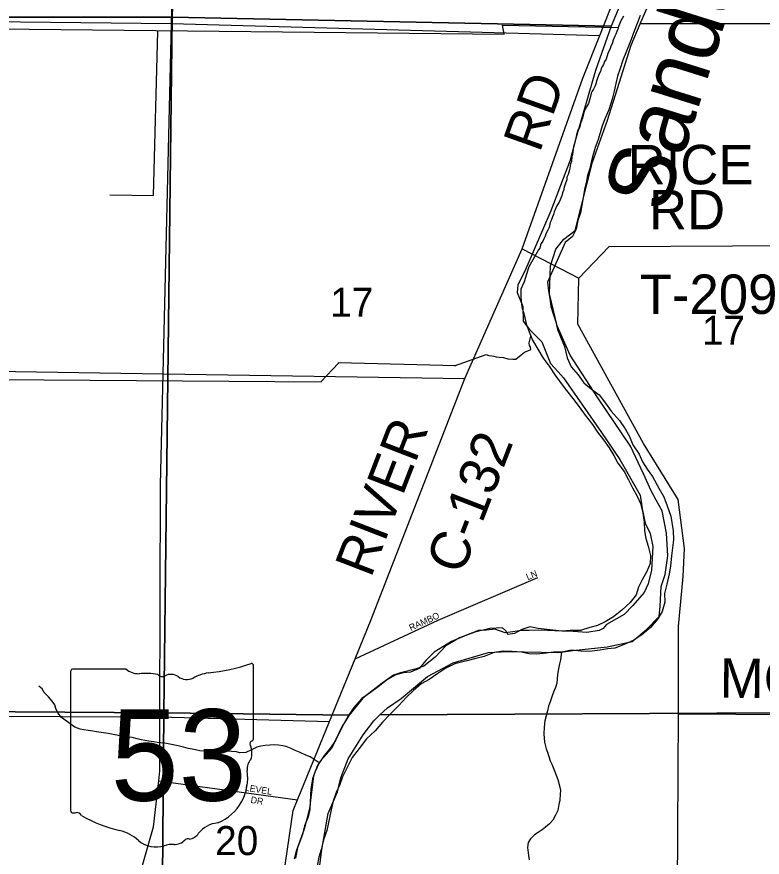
# Model space of a CAD drawing. Extents: x 1588073 to 2013523, y 1090242 to 1357120.
# Drawn here: x 1783629 to 1789302, y 1201342 to 1207738 of the extents above; entities that cross this region are included whole.
import ezdxf

# ---------------------------------------------------------------- set-up
doc = ezdxf.new("R2010")
doc.units = 0
for name, color, linetype in [('GM_X_County_Road', 7, 'Continuous'), ('GM_X_County_Road_Text', 7, 'Continuous'), ('GM_X_Major_River', 7, 'Continuous'), ('GM_X_Major_River_Text', 7, 'Continuous'), ('GM_X_Minor_River', 7, 'Continuous'), ('GM_X_Section', 7, 'Continuous'), ('GM_X_Section_Text', 7, 'Continuous'), ('GM_X_State_Location', 7, 'Continuous'), ('GM_X_State_Route', 7, 'Continuous'), ('GM_X_State_Shield', 7, 'Continuous'), ('GM_X_Township_Road', 7, 'Continuous'), ('GM_X_Township_Road_Text', 7, 'Continuous'), ('GM_X_Township_Subdivision', 7, 'Continuous'), ('GM_X_Township_Subdivision_Text', 7, 'Continuous')]:
    doc.layers.add(name, color=color, linetype=linetype)

msp = doc.modelspace()

# ---------------------------------------------------------------- linework, layer by layer
at = {"layer": 'GM_X_County_Road'}
for points in [[(1787474.9, 1205971.8), (1787936, 1207270.8), (1788064.7, 1207596.9), (1788700.1, 1209207.2), (1788763.4, 1211956.2), (1788825.7, 1212115.9), (1789120.8, 1212441.4), (1789759.7, 1212989.5)], [(1787038, 1204985.7), (1787474.9, 1205971.8)], [(1779562.1, 1205007.3), (1780843.4, 1205083.3), (1782009.9, 1205064.2), (1784742.1, 1205019.5)], [(1784742.1, 1205019.5), (1787038, 1204985.7)], [(1785390.7, 1200052.5), (1785574.5, 1200475), (1785618.1, 1200578.8), (1785660.7, 1201214.2), (1785731.4, 1201696.7), (1785765.2, 1201779.3), (1786008.7, 1202375), (1786203.9, 1202852.3), (1786326.5, 1203152), (1787038, 1204985.7)]]:
    msp.add_lwpolyline(points, dxfattribs=at)
at = {"layer": 'GM_X_Major_River'}
for points in [[(1788245.2, 1207742.7), (1788226.8, 1207706.8), (1788216.5, 1207682.8), (1788208.3, 1207664.9), (1788204.1, 1207642.9), (1788195.9, 1207626.9), (1788187.7, 1207604.9), (1788179.5, 1207591), (1788167.2, 1207561.1), (1788158.9, 1207533.1), (1788148.7, 1207515.1), (1788144.5, 1207497.1), (1788126.1, 1207459.2), (1788113.6, 1207415.3), (1788101.4, 1207397.3), (1788093.1, 1207375.4), (1788085, 1207361.4), (1788076.8, 1207345.5), (1788070.6, 1207321.5), (1788058.3, 1207297.6), (1788043.8, 1207255.6), (1788035.5, 1207227.6), (1788029.4, 1207211.7), (1788017.1, 1207187.7), (1788006.9, 1207171.8), (1788000.7, 1207155.8), (1787994.5, 1207131.8), (1787979.9, 1207077.9), (1787965.6, 1207051.9), (1787947.2, 1207016.1), (1787934.7, 1206966.1), (1787922.4, 1206934.1), (1787912, 1206896.2), (1787899.7, 1206876.2), (1787889.3, 1206840.3), (1787878.8, 1206792.3), (1787870.6, 1206766.3), (1787866.4, 1206748.3), (1787864.2, 1206730.3), (1787857.8, 1206690.2), (1787853.6, 1206674.3), (1787849.2, 1206636.2), (1787843, 1206620.2), (1787834.6, 1206574.2), (1787830.4, 1206556.2), (1787824.2, 1206538.3), (1787815.9, 1206516.3), (1787813.7, 1206496.3), (1787803.5, 1206472.3), (1787795.2, 1206442.3), (1787788.9, 1206416.3), (1787782.7, 1206398.4), (1787776.5, 1206376.4), (1787768.3, 1206358.4), (1787764.1, 1206344.4), (1787755.9, 1206326.5), (1787739.6, 1206298.6), (1787727.3, 1206276.7), (1787719.1, 1206254.7), (1787712.9, 1206232.7), (1787704.7, 1206214.8), (1787694.4, 1206186.8), (1787688.2, 1206172.8), (1787679.8, 1206134.8), (1787669.6, 1206112.9), (1787655.3, 1206087), (1787649.1, 1206069), (1787638.9, 1206047), (1787632.7, 1206031.1), (1787620.5, 1206013.1), (1787614.3, 1205999.2), (1787608.1, 1205977.2), (1787597.9, 1205963.3)], [(1788373.5, 1207747.4), (1788348.9, 1207687.5), (1788326.2, 1207629.6), (1788303.5, 1207565.7), (1788268.6, 1207475.9), (1788239.8, 1207408), (1788217.1, 1207338.1), (1788200.5, 1207286.1), (1788187.9, 1207230.1), (1788175.3, 1207172.1), (1788158.7, 1207110.2), (1788133.8, 1207030.3), (1788107.1, 1206966.4), (1788084.5, 1206908.5), (1788067.9, 1206854.5), (1788051.3, 1206796.6), (1788030.7, 1206742.7), (1788016.2, 1206690.7), (1787999.5, 1206632.7), (1787989, 1206582.7), (1787972.5, 1206530.8), (1787961.9, 1206472.8), (1787949.3, 1206422.8), (1787938.7, 1206362.8), (1787930.1, 1206304.7), (1787919.5, 1206246.7), (1787898.9, 1206188.8), (1787886.2, 1206120.8), (1787857.5, 1206064.9), (1787801, 1206021.4), (1787666.8, 1205717.8)], [(1787597.9, 1205963.3), (1787526.5, 1205835.7), (1787507.9, 1205779.8), (1787489.3, 1205721.8), (1787464.6, 1205663.9), (1787464, 1205601.8), (1787473.3, 1205531.6), (1787488.8, 1205469.3), (1787506.1, 1205401), (1787527.6, 1205340.6), (1787553, 1205278.2), (1787594.4, 1205207.7), (1787633.8, 1205141.1), (1787679.3, 1205078.6), (1787722.8, 1205014), (1787764.3, 1204957.5), (1787811.8, 1204894.9), (1787859.3, 1204834.3), (1787908.8, 1204769.6), (1787954.3, 1204707.1), (1788009.7, 1204634.4), (1788049.2, 1204577.9), (1788094.7, 1204519.3), (1788136.2, 1204456.8), (1788173.7, 1204398.2), (1788203.2, 1204339.8), (1788250.7, 1204277.2), (1788284.1, 1204212.8), (1788315.6, 1204154.3), (1788349.1, 1204089.9), (1788376.6, 1204033.5), (1788393.9, 1203963.1), (1788403.2, 1203892.9), (1788406.6, 1203824.7), (1788416, 1203768.5), (1788433.5, 1203708.2), (1788452.8, 1203637.9), (1788448.2, 1203577.8), (1788423.5, 1203515.9), (1788388.8, 1203452.1), (1788360.2, 1203396.2), (1788341.6, 1203338.3), (1788296.9, 1203280.6), (1788234.2, 1203221.1), (1788169.5, 1203171.6), (1788107, 1203134.1), (1788048.6, 1203106.6), (1787990.3, 1203089.2), (1787919.9, 1203067.8), (1787839.7, 1203068.6), (1787779.5, 1203063.2), (1787667.3, 1203068.3), (1787597.2, 1203071), (1787527, 1203067.7), (1787466.8, 1203066.3), (1787402.6, 1203056.9), (1787346.4, 1203049.4), (1787266.5, 1203078.3), (1787204.3, 1203070.9), (1787142.1, 1203067.5), (1787063.6, 1203038.2), (1787003.2, 1203010.7), (1786936.8, 1202983.3), (1786870.2, 1202943.8), (1786805.7, 1202902.4), (1786740.9, 1202838.9), (1786690.2, 1202779.3), (1786625.7, 1202749.8), (1786569.6, 1202744.4), (1786513.3, 1202728.9), (1786450.8, 1202693.4), (1786378, 1202638), (1786319.5, 1202594.5), (1786254.9, 1202551), (1786194.1, 1202481.5), (1786153.4, 1202419.7), (1786116.6, 1202355.9), (1786083.9, 1202290.1), (1786053.2, 1202230.3), (1786016.6, 1202174.5), (1785969.9, 1202118.8), (1785929.3, 1202061.1), (1785898.6, 1201995.3), (1785877.9, 1201939.3), (1785867.2, 1201863.3), (1785862.2, 1201763.1), (1785857.6, 1201705), (1785845, 1201649), (1785818.3, 1201581.1), (1785803.6, 1201515.1), (1785780.9, 1201455.2), (1785756.3, 1201395.3), (1785739.6, 1201327.3)], [(1787666.8, 1205717.8), (1787675, 1205651.8), (1787684.5, 1205593.6), (1787693.9, 1205533.4), (1787711.4, 1205477.1), (1787730.8, 1205416.8), (1787744.3, 1205358.5), (1787767.8, 1205302.2), (1787797.1, 1205229.7), (1787818.3, 1205141.3), (1787847.7, 1205074.9), (1787901.2, 1205012.2), (1787944.7, 1204951.7), (1788000.4, 1204907.1), (1788062.1, 1204860.3), (1788109.5, 1204797.8), (1788153, 1204737.2), (1788214.5, 1204664.4), (1788260, 1204601.8), (1788291.4, 1204543.4), (1788316.9, 1204481), (1788364.3, 1204408.4), (1788391.8, 1204352), (1788427.3, 1204295.6), (1788466.8, 1204239), (1788514.1, 1204150.4), (1788553.5, 1204085.8), (1788578.9, 1204017.4), (1788606.2, 1203937), (1788625.1, 1203826.6), (1788626.4, 1203758.4), (1788619.8, 1203696.3), (1788611.2, 1203636.3), (1788604.4, 1203558.2), (1788593.8, 1203498.2), (1788577, 1203420.2), (1788558.2, 1203348.2), (1788559.5, 1203282), (1788540.8, 1203212.1), (1788506.2, 1203156.3), (1788451.4, 1203090.7), (1788386.7, 1203035.2), (1788324.1, 1202993.7), (1788251.6, 1202960.3), (1788181.2, 1202933), (1788125, 1202927.5), (1788068.8, 1202918), (1787988.5, 1202906.8), (1787922.4, 1202909.5), (1787850.3, 1202918.2), (1787776, 1202902.9), (1787713.8, 1202901.5), (1787657.6, 1202896), (1787587.3, 1202886.7), (1787525.2, 1202889.3), (1787469.2, 1202901.9), (1787399.1, 1202908.6), (1787331, 1202911.3), (1787262.7, 1202899.9), (1787186.2, 1202870.6), (1787121.9, 1202855.2), (1787053.6, 1202835.8), (1786963.2, 1202812.6), (1786892.7, 1202781.3), (1786832.1, 1202739.8), (1786767.5, 1202694.3), (1786707, 1202660.8), (1786648.4, 1202611.3), (1786591.8, 1202557.7), (1786535, 1202496.1), (1786468.2, 1202428.6), (1786411.5, 1202369.1), (1786356.7, 1202303.5), (1786289.9, 1202242), (1786233.1, 1202170.4), (1786180.3, 1202100.8), (1786141.4, 1202018.9), (1786108.6, 1201953.1), (1786088, 1201895.2), (1786059.3, 1201833.3), (1786036.6, 1201767.4), (1786021.9, 1201701.4), (1786007.3, 1201641.4), (1785988.3, 1201545.4), (1785965.6, 1201481.5), (1785944.8, 1201401.5), (1785928.2, 1201343.5), (1785915.5, 1201275.5)]]:
    msp.add_lwpolyline(points, dxfattribs=at)
at = {"layer": 'GM_X_Minor_River'}
for p, q in [((1782090.2, 1207661.1), (1787337.2, 1207606)), ((1787337.2, 1207606), (1787326.3, 1207674.3)), ((1787326.3, 1207674.3), (1787326.3, 1207674.3)), ((1787326.3, 1207674.3), (1788206.5, 1207655.5)), ((1784669.6, 1206379.2), (1784700.7, 1207626.9)), ((1787337.2, 1207606), (1787337.2, 1207606)), ((1784335.5, 1206382.2), (1784669.6, 1206379.2)), ((1784669.6, 1206379.2), (1784669.6, 1206379.2)), ((1785942.2, 1204960.7), (1786076.7, 1205103)), ((1786076.7, 1205103), (1786076.7, 1205107)), ((1786076.7, 1205107), (1786968.7, 1205083.6)), ((1780250.8, 1205002.4), (1785944.2, 1204960.7)), ((1785944.2, 1204960.7), (1785942.2, 1204960.7))]:
    msp.add_line(p, q, dxfattribs=at)
for points in [[(1786967.1, 1205084.9), (1786959, 1205080.4), (1787200.2, 1205168.3), (1787222, 1205159.9), (1787244, 1205157.6), (1787258, 1205155.4), (1787275.9, 1205149.1), (1787299.8, 1205146.8), (1787331.8, 1205144.3), (1787365.7, 1205135.7), (1787403.6, 1205133.2), (1787427.6, 1205132.8), (1787466.2, 1205164.3), (1787492.6, 1205185.9), (1787518.7, 1205195.6), (1787540.9, 1205205.3), (1787539.2, 1205223.3), (1787529.4, 1205237.5), (1787527.8, 1205255.6), (1787541.6, 1205307.6)], [(1787775.4, 1202902.9), (1787767.4, 1202844.8), (1787759, 1202814.8), (1787750.6, 1202776.8), (1787744.2, 1202732.8), (1787741.8, 1202698.8), (1787737.5, 1202666.7), (1787729.2, 1202634.7), (1787712.8, 1202598.8), (1787702.5, 1202570.9), (1787690.1, 1202532.9), (1787675.6, 1202490.9), (1787667.3, 1202456.9), (1787656.9, 1202419), (1787648.5, 1202381), (1787642, 1202330.9), (1787639.5, 1202280.8), (1787644.9, 1202218.6), (1787656.4, 1202166.4), (1787668.1, 1202140.2), (1787687.5, 1202075.9), (1787701.3, 1202049.7), (1787720.9, 1201999.4), (1787734.6, 1201967.2), (1787746.3, 1201933), (1787761.7, 1201874.7), (1787765.5, 1201848.6), (1787765.2, 1201822.6), (1787760.7, 1201776.5), (1787754.4, 1201742.5), (1787745.9, 1201698.5), (1787729.5, 1201662.6), (1787707.1, 1201624.7), (1787682.8, 1201594.9), (1787652.4, 1201571.1), (1787626.2, 1201549.3), (1787595.9, 1201529.6), (1787569.7, 1201511.8), (1787539.3, 1201482), (1787521, 1201454.1), (1787514.6, 1201416.1), (1787522, 1201353.9), (1787527.7, 1201321.8)], [(1785929.3, 1202061.1), (1785861.6, 1202105.9), (1785827.6, 1202118.2), (1785785.7, 1202138.7), (1785747.8, 1202155.1), (1785717.8, 1202169.4), (1785679.9, 1202183.8), (1785653.9, 1202190.1), (1785619.9, 1202194.4), (1785589.8, 1202196.8), (1785553.7, 1202195.1), (1785517.6, 1202191.4), (1785485.5, 1202187.8), (1785455.3, 1202180), (1785415, 1202158.4), (1785370.7, 1202138.8), (1785326.6, 1202135.2), (1785300.6, 1202143.5), (1785262.6, 1202145.8), (1785232.5, 1202148.1), (1785200.4, 1202148.5), (1785164.3, 1202146.8), (1785122.2, 1202145.2), (1785088.1, 1202143.6), (1785052.1, 1202147.9), (1785022.1, 1202152.2), (1784988, 1202158.6), (1784962, 1202164.8), (1784932, 1202169.1), (1784896, 1202179.5), (1784856, 1202189.9), (1784792, 1202202.6), (1784756, 1202209), (1784726, 1202213.3), (1784695.9, 1202215.6), (1784667.9, 1202219.9), (1784633.9, 1202224.2), (1784601.8, 1202230.5), (1784575.8, 1202234.8), (1784543.8, 1202243.1), (1784507.8, 1202253.5), (1784467.8, 1202257.9), (1784433.8, 1202262.2), (1784401.7, 1202268.6), (1784361.7, 1202275), (1784323.7, 1202283.4), (1784287.7, 1202287.7), (1784235.6, 1202296.3), (1784207.6, 1202300.6), (1784171.6, 1202306.9), (1784137.6, 1202311.3), (1784111.5, 1202315.5), (1784069.6, 1202332), (1783968.1, 1202405.1), (1783940.4, 1202441.5), (1783926.7, 1202473.7), (1783916.9, 1202501.8), (1783897.2, 1202530.1), (1783869.4, 1202562.4), (1783837.7, 1202594.8), (1783821.9, 1202623.1), (1783796, 1202643.3)]]:
    msp.add_lwpolyline(points, dxfattribs=at)
at = {"layer": 'GM_X_Section'}
for points in [[(1779926.5, 1213199.6), (1784959.9, 1213023.4), (1784809.8, 1207735.7), (1779685.1, 1207734.5), (1779923.7, 1213091.5)], [(1784809.8, 1207735.7), (1784747.6, 1202441.3), (1779469.1, 1202477.4), (1779685.1, 1207734.5)], [(1784809.8, 1207735.7), (1788153, 1207666.3), (1788032.4, 1207329), (1787884.4, 1206811.9), (1787839.1, 1206646.1), (1787692.1, 1206261), (1787502.6, 1205820.2), (1787441.7, 1205696.6), (1787437.2, 1205638.6), (1787480.5, 1205532.2), (1787483.6, 1205422.2), (1787531.2, 1205357.8), (1787624.5, 1205265), (1787689.3, 1205098.4), (1787748.8, 1205035.9), (1787788.5, 1204989.6), (1788079.5, 1204573.2), (1788218, 1204368), (1788374, 1204096.7), (1788389.3, 1203994.5), (1788410.4, 1203884.3), (1788447.9, 1203806), (1788469.1, 1203707.8), (1788459.7, 1203525.7), (1788432.9, 1203421.9), (1788402.4, 1203356.1), (1788317.6, 1203256.7), (1788251.1, 1203189.2), (1788192.8, 1203155.6), (1788116.4, 1203112.1), (1788090.2, 1203082.3), (1788062, 1203066.5), (1787965.9, 1203051.3), (1787863.9, 1203060), (1787777.9, 1203062.7), (1787595.9, 1203082.1), (1787532, 1203094.6), (1787471.8, 1203075), (1787417.5, 1203043.4), (1787369.4, 1203035.8), (1787359.6, 1203047.9), (1787349.7, 1203065.9), (1787325.8, 1203088.1), (1787227.7, 1203082.9), (1787113.5, 1203053.7), (1786997.1, 1203010.6), (1786892.6, 1202951.4), (1786811.9, 1202863.9), (1786727.3, 1202796.5), (1786669.1, 1202774.9), (1786548.8, 1202745.8), (1786494.7, 1202728.2), (1786410.2, 1202666.8), (1786261.2, 1202551.9), (1786158.1, 1202422.7), (1784747.6, 1202441.3)], [(1784747.6, 1202441.3), (1784719.2, 1198975.8), (1784570.7, 1198906.9), (1784470.3, 1198863.6), (1784413.8, 1198808), (1784328.8, 1198682.6), (1784195.1, 1198463.5), (1784164.6, 1198393.7), (1784156.1, 1198339.7), (1784123.4, 1198239.9), (1784078.1, 1198078.2), (1784071.6, 1198014.2), (1784086.8, 1197912), (1784099.6, 1197741.8), (1784114.5, 1197605.7), (1784149.2, 1197427.3), (1784217.5, 1197204.7), (1784221.4, 1197188.6), (1784244.9, 1197116.4), (1779354.3, 1197105.5), (1779468.5, 1202448.5), (1779469.1, 1202477.4)]]:
    msp.add_lwpolyline(points, close=True, dxfattribs=at)
for points in [[(1788295.7, 1208013.4), (1788153, 1207666.3), (1784809.8, 1207735.7), (1784959.9, 1213023.4)], [(1790152.3, 1212697.8), (1790048.2, 1207685.9), (1788373.3, 1207684.6), (1788538.2, 1208065.6)], [(1789984.3, 1202443.6), (1786390.3, 1202424.9), (1786448.7, 1202478.5), (1786553.3, 1202549.7), (1786631.9, 1202615.2), (1786754.7, 1202716.3), (1786949.6, 1202820.8), (1787218.3, 1202898.8), (1787362.5, 1202907.8), (1787750.6, 1202898.8), (1787860.8, 1202916), (1788121.1, 1202942), (1788311.5, 1202982.6), (1788422.3, 1203075.8), (1788517.1, 1203173.1), (1788525.7, 1203253.1), (1788532.8, 1203401.1), (1788563.5, 1203493), (1788582.6, 1203636.9), (1788573.9, 1203807), (1788539.2, 1203977.4), (1788495.8, 1204059.8), (1788456.3, 1204130.1), (1788399.3, 1204258.6), (1788298.8, 1204469.5), (1788049.5, 1204837.6), (1787839.8, 1205163.3), (1787741.5, 1205386.2), (1787683.3, 1205628.8), (1787690.9, 1205842.8), (1787729.9, 1205970.6), (1787792.5, 1206046.1), (1787877.1, 1206111.5), (1788011.1, 1206630.8), (1788123.6, 1206952.1), (1788304, 1207523.1), (1788373.3, 1207684.6), (1790048.2, 1207685.9)], [(1784719.2, 1198975.8), (1784747.6, 1202441.3), (1786158.1, 1202422.7), (1786101.5, 1202335), (1786024.2, 1202169.5), (1785941.4, 1202078.1), (1785917.1, 1202040.3), (1785886.5, 1201962.5), (1785878, 1201896.5), (1785856.6, 1201712.6), (1785815.4, 1201554.8), (1785764.3, 1201415.1), (1785749.7, 1201335.2)], [(1785922.6, 1201181.8), (1785950.3, 1201399.7), (1785998.4, 1201673.5), (1786069.7, 1201839), (1786094.5, 1201944.9), (1786151.6, 1202090.5), (1786265.1, 1202273.8), (1786345.9, 1202379.2), (1786390.3, 1202424.9), (1789984.3, 1202443.6), (1789940, 1197137.2)]]:
    msp.add_lwpolyline(points, dxfattribs=at)
at = {"layer": 'GM_X_State_Route'}
msp.add_lwpolyline([(1784330.1, 1200426.4), (1784368.2, 1200514.4), (1784668.1, 1201573.6), (1784708.5, 1201922.3), (1784717.6, 1201999.9), (1784718.3, 1202410.4), (1784721.6, 1204176.5), (1784742.1, 1205019.5), (1784807, 1207686.3), (1784920.9, 1212191.7), (1784921.2, 1212201.9)], dxfattribs=at)
at = {"layer": 'GM_X_State_Shield'}
for p, q in [((1785430.4, 1202245.9), (1785430.4, 1202798.6)), ((1784038.3, 1202754.3), (1784038.3, 1201697.6)), ((1784459.7, 1202772.4), (1784052, 1202772.4)), ((1785430.3, 1202246), (1785430.4, 1202245.9))]:
    msp.add_line(p, q, dxfattribs=at)
for centre, radius, start, end in [((1784934.5, 1204213), 1476.4, 275.84447, 288.90645), ((1785415, 1202800.9), 15.5, 351.86209, 97.738), ((1784054.2, 1202756.5), 16.1, 98.1301, 188.1301), ((1784556.8, 1202895.1), 156.4, 231.61951, 271.11188), ((1784608.6, 1202179.2), 561.6, 80.48669, 94.98827), ((1784736.1, 1202762), 45.1, 219.79206, 297.10237), ((1784802.4, 1202639.9), 93.8, 54.46668, 119.14113), ((1785122.8, 1202449.7), 297, 97.34618, 120.76885), ((1784923.5, 1202807.4), 112.9, 233.85621, 294.82819), ((1785426.9, 1202205.3), 24, 107.94398, 210.33697), ((1785413.9, 1202243.8), 16.6, 289.60381, 7.73413), ((1785274.3, 1202135.4), 144, 340.03296, 23.64957), ((1785486, 1202014.6), 104.8, 136.8065, 186.92959), ((1785017.2, 1201944.3), 369.3, 292.30889, 8.98584), ((1784054.4, 1201695.3), 16.3, 171.95839, 258.30661), ((1784056.8, 1201803.4), 124.2, 267.33899, 280.60386), ((1784082.2, 1201636.7), 44.8, 29.74838, 93.27175), ((1784647.5, 1202586), 1066.1, 240.41292, 257.1985), ((1785172.9, 1201401), 202.2, 94.40312, 142.57675), ((1784329.7, 1201222.9), 333.6, 47.18416, 75.83597), ((1784916.7, 1201595.2), 119.3, 282.87319, 323.27711), ((1784690.4, 1201631.4), 211.7, 230.70037, 286.29184), ((1784812.8, 1201266.1), 173.9, 85.69512, 111.20995), ((1784828.2, 1201552.3), 112.8, 268.77702, 315.54927), ((1784930.2, 1201450), 31.8, 65.75173, 132.64842)]:
    msp.add_arc(centre, radius, start, end, dxfattribs=at)
at = {"layer": 'GM_X_Township_Road'}
for points in [[(1782043.8, 1207716.7), (1784807, 1207686.3)], [(1784807, 1207686.3), (1787444.2, 1207613.9), (1787444.2, 1207613.9)], [(1787444.2, 1207613.9), (1788064.7, 1207596.9)], [(1787905.3, 1205748.9), (1788137.2, 1205990.9), (1790013.8, 1205999.1)], [(1787474.9, 1205971.8), (1787905.3, 1205748.9)], [(1788648.3, 1199763.2), (1788664.4, 1202432.7), (1788663.4, 1203098.6), (1788700.6, 1203477.3), (1788709.4, 1203691.8), (1788661.6, 1204065.4), (1788397.7, 1204489.4), (1787898.6, 1205398), (1787905.3, 1205748.9)], [(1779486.2, 1202436.4), (1779488.7, 1202438), (1779503.4, 1202445), (1779526.7, 1202451.2), (1781755.6, 1202421.1), (1784718.3, 1202410.4)], [(1784718.3, 1202410.4), (1786008.7, 1202375)], [(1788664.4, 1202432.7), (1789973.3, 1202425), (1793235.2, 1202405.6)]]:
    msp.add_lwpolyline(points, dxfattribs=at)
at = {"layer": 'GM_X_Township_Subdivision'}
for points in [[(1786203.9, 1202852.3), (1786835.6, 1203146.1), (1787593.8, 1203470.1)], [(1784708.5, 1201922.3), (1785765.2, 1201779.3)]]:
    msp.add_lwpolyline(points, dxfattribs=at)

# ---------------------------------------------------------------- texts
at = {"layer": 'GM_X_County_Road_Text'}
for s, rotation, p in [('RD', 70.31385, (1787607.3, 1206697.2)), ('RIVER', 68.88009, (1786323.5, 1203461.6)), ('C-132', 68.86342, (1787016.6, 1203481.9))]:
    msp.add_text(s, height=300, rotation=rotation, dxfattribs=at).set_placement(p)
at = {"layer": 'GM_X_Major_River_Text'}
msp.add_text('Sandusky', height=500.21, rotation=72.59642, dxfattribs=at).set_placement((1788562.2, 1206233.3))
at = {"layer": 'GM_X_Section_Text'}
for s, p in [('17', (1786013.5, 1205454.9)), ('17', (1788842.7, 1205241.5)), ('20', (1785137.8, 1201358))]:
    msp.add_text(s, height=221, rotation=0.00001, dxfattribs=at).set_placement(p)
at = {"layer": 'GM_X_State_Location'}
for s in ['s', 'r']:
    msp.add_text(s, height=1, dxfattribs=at).set_placement((1784718.7, 1202155.7))
msp.add_text('53', height=1, rotation=0.00001, dxfattribs=at).set_placement((1784466.9, 1202082.9))
at = {"layer": 'GM_X_State_Shield'}
msp.add_text('53', height=696.1, dxfattribs=at).set_placement((1784343, 1201772.1))
at = {"layer": 'GM_X_Township_Road_Text'}
for s, rotation, p in [('RICE', 0.00001, (1788277.2, 1206463.1)), ('RD', 0.00001, (1788440, 1206119.7)), ('T-209', 0.00001, (1788369.6, 1205476.7)), ('MC', 359.55868, (1788977.8, 1202555.9))]:
    msp.add_text(s, height=300, rotation=rotation, dxfattribs=at).set_placement(p)
at = {"layer": 'GM_X_Township_Subdivision_Text'}
for s, rotation, p in [('LN', 22.37755, (1787516.9, 1203449.7)), ('RAMBO', 24.53696, (1786627.7, 1203062.4)), ('LEVEL', 350.9603, (1785361.5, 1201848.7)), ('DR', 351.02531, (1785405.4, 1201755.9))]:
    msp.add_text(s, height=50, rotation=rotation, dxfattribs=at).set_placement(p)

doc.saveas('drawing.dxf')
